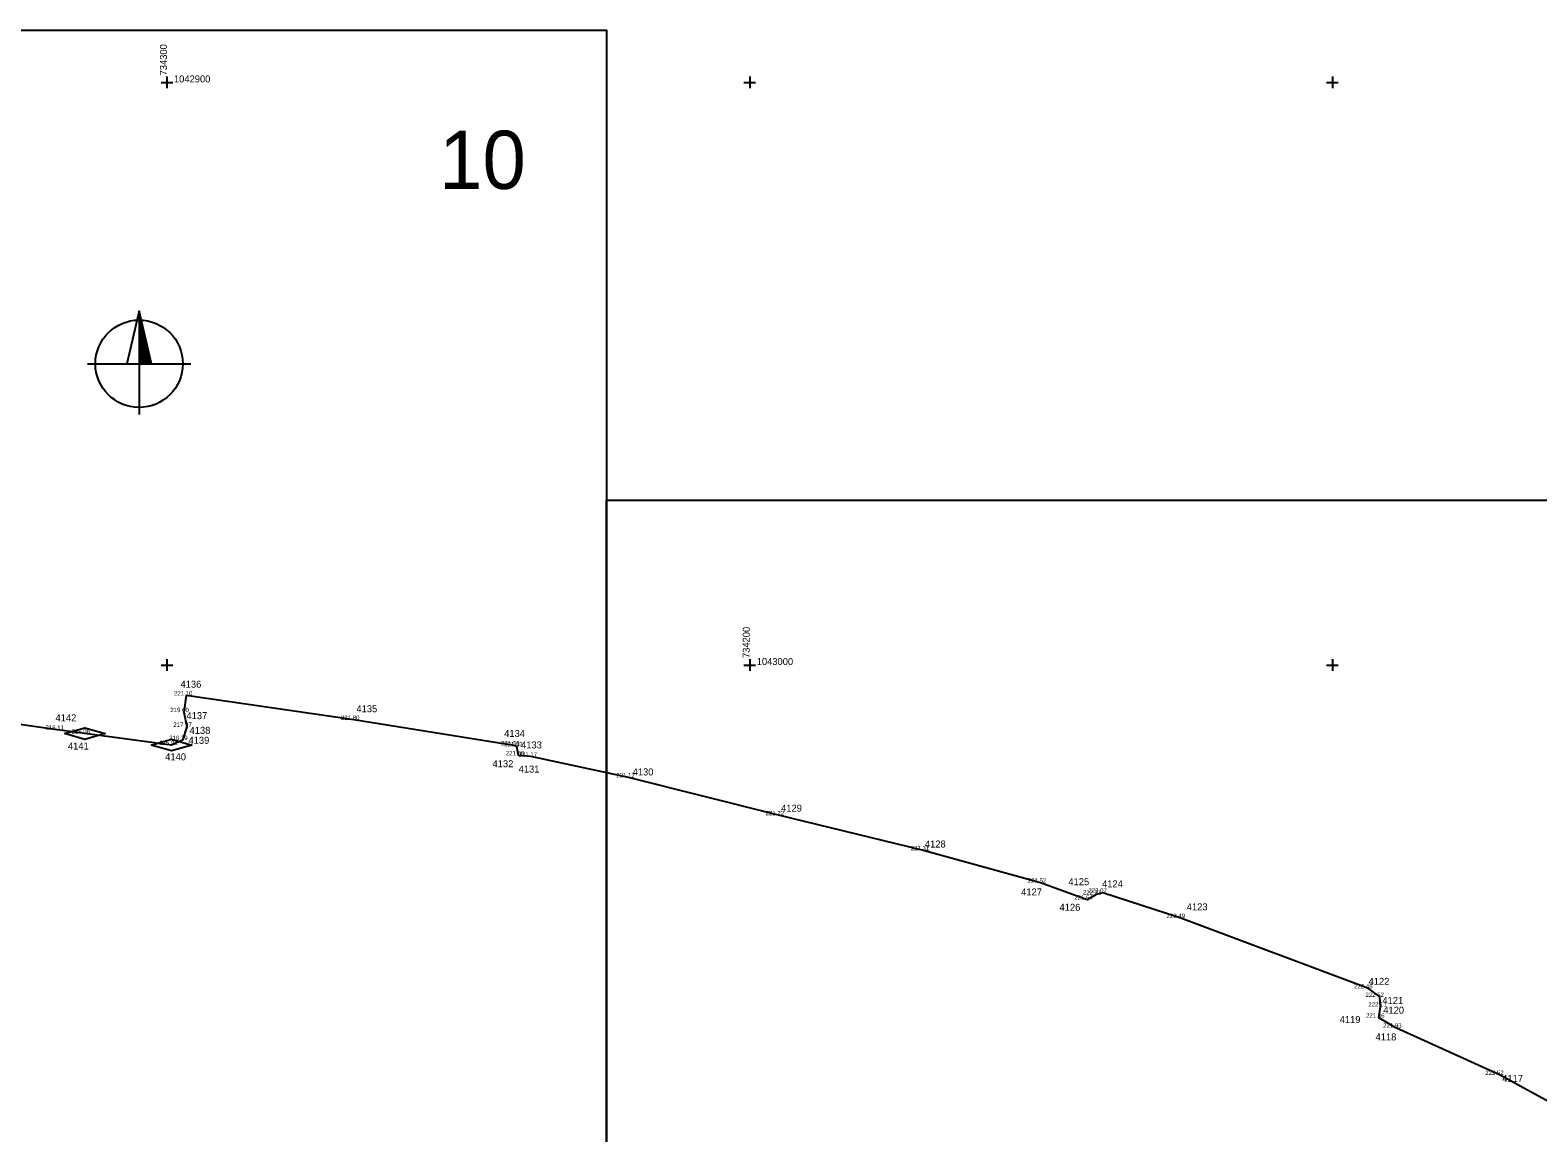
# Model space of a CAD drawing. Extents: x -736532 to -730799, y -1045301 to -1042399.
# Drawn here: x -734323.5 to -734064.8, y -1043080.3 to -1042891 of the extents above; entities that cross this region are included whole.
import ezdxf

# ---------------------------------------------------------------- set-up
doc = ezdxf.new("R2010")
doc.units = 0
for name, color, linetype in [('Vrstva 26', 7, 'Continuous'), ('Vrstva 50', 7, 'Continuous'), ('Vrstva 60', 7, 'Continuous'), ('Vrstva 61', 7, 'Continuous'), ('Vrstva 62', 7, 'Continuous'), ('Vrstva 63', 7, 'Continuous')]:
    doc.layers.add(name, color=color, linetype=linetype)

msp = doc.modelspace()

# ---------------------------------------------------------------- linework, layer by layer
at = {"layer": 'Vrstva 26'}
for points in [[(-734059.72, -1043076.7), (-734071.32, -1043070.36), (-734089.12, -1043062.25), (-734092.05, -1043060.53), (-734091.73, -1043058.64), (-734091.88, -1043056.97), (-734093.83, -1043055.51), (-734126.01, -1043043.43), (-734139.43, -1043039.08), (-734140.57, -1043039.4), (-734142.09, -1043040.28), (-734150.08, -1043037.37), (-734170.38, -1043031.8), (-734195.06, -1043025.79), (-734220.82, -1043019.29), (-734237.57, -1043015.72), (-734239.67, -1043015.5), (-734239.96, -1043013.96), (-734240.48, -1043013.81), (-734267.93, -1043009.43), (-734296.72, -1043005.22), (-734297.1, -1043008.09), (-734296.57, -1043010.61), (-734297.31, -1043012.88), (-734299.21, -1043013.75), (-734314.08, -1043011.77), (-734318.87, -1043011.12), (-734330.11, -1043009.53)], [(-734239.96, -1043013.96), (-734240.48, -1043013.81), (-734267.93, -1043009.43), (-734296.72, -1043005.22)], [(-734317.58, -1043011.77), (-734314.08, -1043010.77), (-734310.58, -1043011.77), (-734314.08, -1043012.77), (-734317.58, -1043011.77)], [(-734302.71, -1043013.75), (-734299.21, -1043012.75), (-734295.71, -1043013.75), (-734299.21, -1043014.75), (-734302.71, -1043013.75)], [(-734091.73, -1043058.64), (-734091.88, -1043056.97), (-734093.83, -1043055.51), (-734126.01, -1043043.43), (-734139.43, -1043039.08), (-734140.57, -1043039.4)]]:
    msp.add_lwpolyline(points, dxfattribs=at)
at = {"layer": 'Vrstva 50'}
for p, q in [((-734304.78, -1042939.19), (-734306.91, -1042948.29)), ((-734302.65, -1042948.29), (-734304.78, -1042939.19)), ((-734304.78, -1042939.19), (-734304.78, -1042957)), ((-734304.78, -1042939.54), (-734304.7, -1042939.54)), ((-734304.78, -1042939.67), (-734304.67, -1042939.67)), ((-734304.78, -1042939.79), (-734304.64, -1042939.79)), ((-734304.78, -1042939.92), (-734304.61, -1042939.92)), ((-734304.78, -1042940.04), (-734304.58, -1042940.04)), ((-734304.78, -1042940.17), (-734304.55, -1042940.17)), ((-734304.78, -1042940.29), (-734304.52, -1042940.29)), ((-734304.78, -1042940.42), (-734304.49, -1042940.42)), ((-734304.78, -1042940.54), (-734304.46, -1042940.54)), ((-734304.78, -1042940.67), (-734304.44, -1042940.67)), ((-734304.78, -1042940.79), (-734304.41, -1042940.79)), ((-734304.78, -1042940.92), (-734304.38, -1042940.92)), ((-734304.78, -1042941.04), (-734304.35, -1042941.04)), ((-734304.78, -1042941.17), (-734304.32, -1042941.17)), ((-734304.78, -1042941.29), (-734304.29, -1042941.29)), ((-734304.78, -1042941.42), (-734304.26, -1042941.42)), ((-734304.78, -1042941.54), (-734304.23, -1042941.54)), ((-734304.78, -1042941.67), (-734304.2, -1042941.67)), ((-734304.78, -1042941.79), (-734304.17, -1042941.79)), ((-734304.78, -1042941.92), (-734304.14, -1042941.92)), ((-734304.78, -1042942.04), (-734304.11, -1042942.04)), ((-734304.78, -1042942.17), (-734304.08, -1042942.17)), ((-734304.78, -1042942.29), (-734304.06, -1042942.29)), ((-734304.78, -1042942.42), (-734304.03, -1042942.42)), ((-734304.78, -1042942.54), (-734304, -1042942.54)), ((-734304.78, -1042942.67), (-734303.97, -1042942.67)), ((-734304.78, -1042942.79), (-734303.94, -1042942.79)), ((-734304.78, -1042942.92), (-734303.91, -1042942.92)), ((-734304.78, -1042943.04), (-734303.88, -1042943.04)), ((-734304.78, -1042943.17), (-734303.85, -1042943.17)), ((-734304.78, -1042943.29), (-734303.82, -1042943.29)), ((-734304.78, -1042943.42), (-734303.79, -1042943.42)), ((-734304.78, -1042943.54), (-734303.76, -1042943.54)), ((-734304.78, -1042943.67), (-734303.73, -1042943.67)), ((-734304.78, -1042943.79), (-734303.7, -1042943.79)), ((-734304.78, -1042943.92), (-734303.68, -1042943.92)), ((-734304.78, -1042944.04), (-734303.65, -1042944.04)), ((-734304.78, -1042944.17), (-734303.62, -1042944.17)), ((-734304.78, -1042944.29), (-734303.59, -1042944.29)), ((-734304.78, -1042944.42), (-734303.56, -1042944.42)), ((-734304.78, -1042944.54), (-734303.53, -1042944.54)), ((-734304.78, -1042944.67), (-734303.5, -1042944.67)), ((-734304.78, -1042944.79), (-734303.47, -1042944.79)), ((-734304.78, -1042944.92), (-734303.44, -1042944.92)), ((-734304.78, -1042945.04), (-734303.41, -1042945.04)), ((-734304.78, -1042945.17), (-734303.38, -1042945.17)), ((-734304.78, -1042945.29), (-734303.35, -1042945.29)), ((-734304.78, -1042945.42), (-734303.33, -1042945.42)), ((-734304.78, -1042945.54), (-734303.3, -1042945.54)), ((-734304.78, -1042945.67), (-734303.27, -1042945.67)), ((-734304.78, -1042945.79), (-734303.24, -1042945.79)), ((-734304.78, -1042945.92), (-734303.21, -1042945.92)), ((-734313.66, -1042948.29), (-734295.9, -1042948.29)), ((-734304.78, -1042946.04), (-734303.18, -1042946.04)), ((-734304.78, -1042946.17), (-734303.15, -1042946.17)), ((-734304.78, -1042946.29), (-734303.12, -1042946.29)), ((-734304.78, -1042946.42), (-734303.09, -1042946.42)), ((-734304.78, -1042946.54), (-734303.06, -1042946.54)), ((-734304.78, -1042946.67), (-734303.03, -1042946.67)), ((-734304.78, -1042946.79), (-734303, -1042946.79)), ((-734304.78, -1042946.92), (-734302.97, -1042946.92)), ((-734304.78, -1042947.04), (-734302.95, -1042947.04)), ((-734304.78, -1042947.17), (-734302.92, -1042947.17)), ((-734304.78, -1042947.29), (-734302.89, -1042947.29)), ((-734304.78, -1042947.42), (-734302.86, -1042947.42)), ((-734304.78, -1042947.54), (-734302.83, -1042947.54)), ((-734304.78, -1042947.67), (-734302.8, -1042947.67)), ((-734304.78, -1042947.79), (-734302.77, -1042947.79)), ((-734304.78, -1042947.92), (-734302.74, -1042947.92)), ((-734304.78, -1042948.04), (-734302.71, -1042948.04)), ((-734304.78, -1042948.17), (-734302.68, -1042948.17))]:
    msp.add_line(p, q, dxfattribs=at)
msp.add_circle((-734304.78, -1042948.29), 7.5, dxfattribs=at)
at = {"layer": 'Vrstva 60'}
for p, q in [((-734296.72, -1043005.22), (-734296.72, -1043005.22)), ((-734297.1, -1043008.09), (-734297.1, -1043008.09)), ((-734296.57, -1043010.61), (-734296.57, -1043010.61)), ((-734267.93, -1043009.43), (-734267.93, -1043009.43)), ((-734318.87, -1043011.12), (-734318.87, -1043011.12)), ((-734314.08, -1043011.77), (-734314.08, -1043011.77)), ((-734297.31, -1043012.88), (-734297.31, -1043012.88)), ((-734299.21, -1043013.75), (-734299.21, -1043013.75)), ((-734240.48, -1043013.81), (-734240.48, -1043013.81)), ((-734239.96, -1043013.96), (-734239.96, -1043013.96)), ((-734239.67, -1043015.5), (-734239.67, -1043015.5)), ((-734237.57, -1043015.72), (-734237.57, -1043015.72)), ((-734220.82, -1043019.29), (-734220.82, -1043019.29)), ((-734195.06, -1043025.79), (-734195.06, -1043025.79)), ((-734170.38, -1043031.8), (-734170.38, -1043031.8)), ((-734150.08, -1043037.37), (-734150.08, -1043037.37)), ((-734139.43, -1043039.08), (-734139.43, -1043039.08)), ((-734142.09, -1043040.28), (-734142.09, -1043040.28)), ((-734140.57, -1043039.4), (-734140.57, -1043039.4)), ((-734126.01, -1043043.43), (-734126.01, -1043043.43)), ((-734093.83, -1043055.51), (-734093.83, -1043055.51)), ((-734091.88, -1043056.97), (-734091.88, -1043056.97)), ((-734091.73, -1043058.64), (-734091.73, -1043058.64)), ((-734092.05, -1043060.53), (-734092.05, -1043060.53)), ((-734089.12, -1043062.25), (-734089.12, -1043062.25)), ((-734071.32, -1043070.36), (-734071.32, -1043070.36))]:
    msp.add_line(p, q, dxfattribs=at)
at = {"layer": 'Vrstva 61'}
for p, q in [((-734300, -1042899), (-734300, -1042901)), ((-734200, -1042899), (-734200, -1042901)), ((-734100, -1042899), (-734100, -1042901)), ((-734301, -1042900), (-734299, -1042900)), ((-734201, -1042900), (-734199, -1042900)), ((-734101, -1042900), (-734099, -1042900)), ((-734301, -1043000), (-734299, -1043000)), ((-734300, -1042999), (-734300, -1043001)), ((-734201, -1043000), (-734199, -1043000)), ((-734200, -1042999), (-734200, -1043001)), ((-734101, -1043000), (-734099, -1043000)), ((-734100, -1042999), (-734100, -1043001))]:
    msp.add_line(p, q, dxfattribs=at)
at = {"layer": 'Vrstva 63'}
for points in [[(-734628.7, -1042891.03), (-734224.58, -1042891.03), (-734224.58, -1043169.99), (-734628.7, -1043169.99)], [(-734224.58, -1042971.71), (-733820.45, -1042971.71), (-733820.45, -1043250.67), (-734224.58, -1043250.67)]]:
    msp.add_lwpolyline(points, close=True, dxfattribs=at)

# ---------------------------------------------------------------- texts
at = {"layer": 'Vrstva 61'}
for s, p in [(' 4136', (-734298.12, -1043003.89)), (' 4135', (-734267.93, -1043008.1)), (' 4142', (-734319.57, -1043009.66)), (' 4137', (-734297.1, -1043009.29)), (' 4138', (-734296.57, -1043011.81)), (' 4139', (-734296.75, -1043013.52)), (' 4134', (-734242.58, -1043012.34)), (' 4133', (-734239.68, -1043014.32)), (' 4141', (-734317.44, -1043014.51)), (' 4140', (-734300.75, -1043016.35)), (' 4132', (-734244.58, -1043017.54)), (' 4131', (-734240.1, -1043018.46)), (' 4130', (-734220.54, -1043018.95)), (' 4129', (-734195.06, -1043025.17)), (' 4128', (-734170.38, -1043031.32)), (' 4127', (-734153.87, -1043039.55)), (' 4125', (-734145.76, -1043037.79)), (' 4124', (-734139.99, -1043038.17)), (' 4126', (-734147.28, -1043042.18)), (' 4123', (-734125.45, -1043042.1)), (' 4122', (-734094.25, -1043054.89)), (' 4121', (-734091.88, -1043058.17)), (' 4120', (-734091.73, -1043059.84)), (' 4119', (-734099.21, -1043061.45)), (' 4118', (-734093.05, -1043064.43)), (' 4117', (-734071.32, -1043071.56))]:
    msp.add_text(s, height=1.2, dxfattribs=at).set_placement(p)
at = {"layer": 'Vrstva 62'}
for s, p in [('221 10 ', (-734298.8, -1043005.22)), ('219 60 ', (-734299.42, -1043008.09)), ('216 11 ', (-734320.84, -1043011.12)), ('217 97 ', (-734298.9, -1043010.61)), ('221 80 ', (-734270.14, -1043009.43)), ('216 06 ', (-734316.38, -1043011.77)), ('215 91 ', (-734301.33, -1043013.75)), ('216 79 ', (-734299.62, -1043012.88)), ('221 56 ', (-734242.67, -1043013.81)), ('221 33 ', (-734242.13, -1043013.96)), ('221 06 ', (-734241.86, -1043015.5)), ('221 17 ', (-734239.65, -1043015.72)), ('221 12 ', (-734222.9, -1043019.29)), ('221 22 ', (-734197.27, -1043025.79)), ('221 31 ', (-734172.36, -1043031.8)), ('221 52 ', (-734152.29, -1043037.37)), ('222 21 ', (-734142.82, -1043039.4)), ('222 07 ', (-734141.89, -1043039.08)), ('221 54 ', (-734144.3, -1043040.28)), ('222 49 ', (-734128.47, -1043043.43)), ('222 46 ', (-734096.28, -1043055.51)), ('222 52 ', (-734094.34, -1043056.97)), ('221 86 ', (-734094.24, -1043060.53)), ('222 11 ', (-734093.85, -1043058.64)), ('221 93 ', (-734091.31, -1043062.25)), ('222 52 ', (-734073.78, -1043070.36))]:
    msp.add_text(s, height=0.75, dxfattribs=at).set_placement(p)
at = {"layer": 'Vrstva 63'}
for s, p in [('734300', (-734300, -1042898.8)), ('734200', (-734200, -1042998.8))]:
    msp.add_text(s, height=1.2, rotation=90, dxfattribs=at).set_placement(p)
for s, height, p in [('1042900', 1.2, (-734298.8, -1042900)), ('10', 10, (-734253.29, -1042918.29)), ('1043000', 1.2, (-734198.8, -1043000))]:
    msp.add_text(s, height=height, dxfattribs=at).set_placement(p)

doc.saveas('drawing.dxf')
